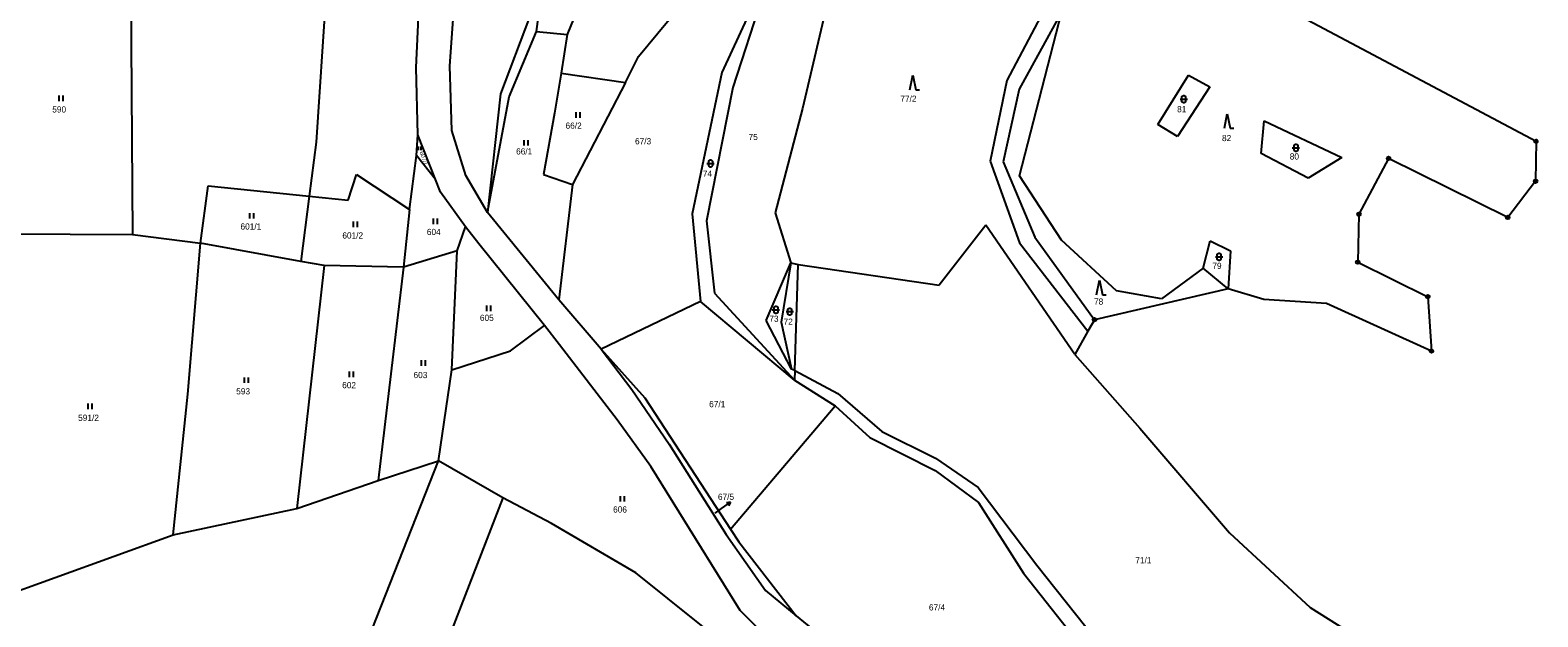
# Model space of a CAD drawing. Extents: x -794421 to -792735, y -1117671 to -1115559.
# Drawn here: x -793344.4 to -792931.3, y -1117405.7 to -1117244.8 of the extents above; entities that cross this region are included whole.
import ezdxf

# ---------------------------------------------------------------- set-up
doc = ezdxf.new("R2010")
doc.units = 0
for name, color, linetype in [('Komunikace', 7, 'Continuous'), ('Vrstva 1', 7, 'Continuous'), ('Vrstva 14', 7, 'Continuous'), ('Vrstva 16', 7, 'Continuous'), ('Vrstva 23', 7, 'Continuous'), ('Vrstva 28', 7, 'Continuous'), ('Vrstva 4', 7, 'Continuous')]:
    doc.layers.add(name, color=color, linetype=linetype)

msp = doc.modelspace()

# ---------------------------------------------------------------- linework, layer by layer
at = {"layer": 'Komunikace'}
msp.add_line((-793156.69, -1117377.21), (-793154.95, -1117375.97), dxfattribs=at)
at = {"layer": 'Vrstva 1'}
for p, q in [((-793260.9, -1117198.31), (-793266.07, -1117275.47)), ((-793238.67, -1117254.97), (-793236.5, -1117210.76)), ((-793229.4, -1117254.52), (-793226.18, -1117209.72)), ((-793205.62, -1117245.12), (-793201.81, -1117214.94)), ((-793316.98, -1117218.04), (-793316.4, -1117300.84)), ((-793185.17, -1117216.32), (-793197.22, -1117245.93)), ((-793140.12, -1117224.4), (-793154.91, -1117256.34)), ((-793140.12, -1117224.4), (-793151.88, -1117260.51)), ((-793177.68, -1117252.02), (-793160.21, -1117230.85)), ((-793124.49, -1117230.97), (-793132.78, -1117266.28)), ((-793066.62, -1117239.34), (-793076.81, -1117258.54)), ((-793061.68, -1117239.68), (-793073.4, -1117260.98)), ((-793073.28, -1117284.7), (-793061.68, -1117239.68)), ((-793207.55, -1117241.17), (-793215.51, -1117262.2)), ((-793213.19, -1117263.04), (-793205.62, -1117245.12)), ((-793205.62, -1117245.12), (-793197.22, -1117245.93)), ((-793197.22, -1117245.93), (-793198.88, -1117256.57)), ((-793181.29, -1117259.16), (-793177.68, -1117252.02)), ((-793238.16, -1117273.44), (-793238.67, -1117254.97)), ((-793228.88, -1117272.27), (-793229.4, -1117254.52)), ((-793198.88, -1117256.57), (-793200.71, -1117267.55)), ((-793198.88, -1117256.57), (-793181.29, -1117259.16)), ((-793154.91, -1117256.34), (-793162.97, -1117295.13)), ((-793181.29, -1117259.16), (-793195.79, -1117287.12)), ((-793151.88, -1117260.51), (-793159.06, -1117297.11)), ((-793076.81, -1117258.54), (-793081.38, -1117280.68)), ((-793035.38, -1117270.69), (-793026.97, -1117257.13)), ((-793021.19, -1117260.36), (-793030.06, -1117273.9)), ((-793026.97, -1117257.13), (-793021.19, -1117260.36)), ((-793215.51, -1117262.2), (-793219.06, -1117294.74)), ((-793219.06, -1117294.74), (-793213.19, -1117263.04)), ((-793073.4, -1117260.98), (-793077.81, -1117280.91)), ((-793200.71, -1117267.55), (-793203.78, -1117284.33)), ((-793132.78, -1117266.28), (-793140.29, -1117294.91)), ((-793224.98, -1117284.66), (-793228.88, -1117272.27)), ((-793030.06, -1117273.9), (-793035.38, -1117270.69)), ((-793007.13, -1117278.56), (-793006.27, -1117269.65)), ((-793006.27, -1117269.65), (-792985.02, -1117279.68)), ((-793266.07, -1117275.47), (-793267.95, -1117290.3)), ((-793238.58, -1117279.17), (-793238.16, -1117273.44)), ((-793233.31, -1117285.75), (-793238.16, -1117273.44)), ((-793240.45, -1117293.93), (-793238.58, -1117279.17)), ((-793233.31, -1117285.75), (-793238.58, -1117279.17)), ((-793081.38, -1117280.68), (-793073.29, -1117303.06)), ((-793077.81, -1117280.91), (-793069.13, -1117301.58)), ((-792994.18, -1117285.34), (-793007.13, -1117278.56)), ((-792985.02, -1117279.68), (-792994.18, -1117285.34)), ((-793257.31, -1117291.39), (-793254.98, -1117284.33)), ((-793254.98, -1117284.33), (-793240.45, -1117293.93)), ((-793219.06, -1117294.74), (-793224.98, -1117284.66)), ((-793203.78, -1117284.33), (-793195.79, -1117287.12)), ((-793061.82, -1117302.35), (-793073.28, -1117284.7)), ((-793297.72, -1117303.18), (-793295.63, -1117287.48)), ((-793295.63, -1117287.48), (-793267.95, -1117290.3)), ((-793231.95, -1117289.21), (-793233.31, -1117285.75)), ((-793225.14, -1117298.73), (-793231.95, -1117289.21)), ((-793195.79, -1117287.12), (-793199.58, -1117318.7)), ((-793267.95, -1117290.3), (-793270.21, -1117308.18)), ((-793267.95, -1117290.3), (-793257.31, -1117291.39)), ((-793240.45, -1117293.93), (-793242.13, -1117309.8)), ((-793199.58, -1117318.7), (-793219.06, -1117294.74)), ((-793162.97, -1117295.13), (-793160.75, -1117319.21)), ((-793159.06, -1117297.11), (-793156.85, -1117316.94)), ((-793140.29, -1117294.91), (-793135.99, -1117308.56)), ((-793350.56, -1117300.6), (-793316.4, -1117300.84)), ((-793316.4, -1117300.84), (-793297.72, -1117303.18)), ((-793227.44, -1117305.29), (-793225.14, -1117298.73)), ((-793221.42, -1117303.41), (-793225.14, -1117298.73)), ((-793082.51, -1117298.26), (-793095.28, -1117314.74)), ((-793058.15, -1117333.75), (-793082.51, -1117298.26)), ((-793069.13, -1117301.58), (-793052.78, -1117324.18)), ((-793301.19, -1117344.58), (-793297.72, -1117303.18)), ((-793270.21, -1117308.18), (-793297.72, -1117303.18)), ((-793227.44, -1117305.29), (-793242.13, -1117309.8)), ((-793228.88, -1117337.91), (-793227.44, -1117305.29)), ((-793203.49, -1117325.78), (-793221.42, -1117303.41)), ((-793073.29, -1117303.06), (-793054.62, -1117327.3)), ((-793046.75, -1117316.31), (-793061.82, -1117302.35)), ((-793023.01, -1117310.05), (-793021.11, -1117302.53)), ((-793021.11, -1117302.53), (-793015.54, -1117305.32)), ((-793015.54, -1117305.32), (-793016.16, -1117315.69)), ((-793263.8, -1117309.35), (-793271.37, -1117375.94)), ((-793263.8, -1117309.35), (-793270.21, -1117308.18)), ((-793242.13, -1117309.8), (-793263.8, -1117309.35)), ((-793242.13, -1117309.8), (-793249.06, -1117368.3)), ((-793142.76, -1117324.44), (-793135.99, -1117308.56)), ((-793135.99, -1117308.56), (-793138.59, -1117324.87)), ((-793135.99, -1117308.56), (-793133.98, -1117309.03)), ((-793134.88, -1117338.16), (-793133.98, -1117309.03)), ((-793133.98, -1117309.03), (-793095.28, -1117314.74)), ((-793023.01, -1117310.05), (-793034.37, -1117318.45)), ((-793016.16, -1117315.69), (-793023.01, -1117310.05)), ((-793156.85, -1117316.94), (-793134.94, -1117340.8)), ((-793034.37, -1117318.45), (-793046.75, -1117316.31)), ((-793187.95, -1117332.28), (-793199.58, -1117318.7)), ((-793160.75, -1117319.21), (-793187.95, -1117332.28)), ((-793134.94, -1117340.8), (-793160.75, -1117319.21)), ((-793212.82, -1117332.77), (-793203.49, -1117325.78)), ((-793199.36, -1117331.07), (-793203.49, -1117325.78)), ((-793135.77, -1117337.72), (-793142.76, -1117324.44)), ((-793138.59, -1117324.87), (-793135.77, -1117337.72)), ((-793228.88, -1117337.91), (-793212.82, -1117332.77)), ((-793183.54, -1117351.62), (-793199.36, -1117331.07)), ((-793187.95, -1117332.28), (-793179.51, -1117343.3)), ((-793187.95, -1117332.28), (-793175.97, -1117345.66)), ((-793232.53, -1117362.94), (-793228.88, -1117337.91)), ((-793134.88, -1117338.16), (-793135.77, -1117337.72)), ((-793134.88, -1117338.16), (-793134.94, -1117340.8)), ((-793134.88, -1117338.16), (-793123.08, -1117344.47)), ((-793179.51, -1117343.3), (-793169.32, -1117358.3)), ((-793134.94, -1117340.8), (-793123.84, -1117347.81)), ((-793305.2, -1117383.22), (-793301.19, -1117344.58)), ((-793175.97, -1117345.66), (-793152.46, -1117381.62)), ((-793123.08, -1117344.47), (-793111.04, -1117354.84)), ((-793152.46, -1117381.62), (-793123.84, -1117347.81)), ((-793123.84, -1117347.81), (-793114.3, -1117356.53)), ((-793174.35, -1117364.49), (-793183.54, -1117351.62)), ((-793111.04, -1117354.84), (-793096.35, -1117362.17)), ((-793169.32, -1117358.3), (-793153.71, -1117383.1)), ((-793114.3, -1117356.53), (-793096.39, -1117365.52)), ((-793286.1, -1117499.19), (-793232.53, -1117362.94)), ((-793249.06, -1117368.3), (-793232.53, -1117362.94)), ((-793214.85, -1117373.01), (-793232.53, -1117362.94)), ((-793096.35, -1117362.17), (-793084.66, -1117370.19)), ((-793149.83, -1117403.92), (-793174.35, -1117364.49)), ((-793096.39, -1117365.52), (-793084.58, -1117374.33)), ((-793271.37, -1117375.94), (-793249.06, -1117368.3)), ((-793084.66, -1117370.19), (-793068.56, -1117391.53)), ((-793305.2, -1117383.22), (-793271.37, -1117375.94)), ((-793214.85, -1117373.01), (-793268.27, -1117510.87)), ((-793201.55, -1117380.12), (-793214.85, -1117373.01)), ((-793084.58, -1117374.33), (-793072.2, -1117393.73)), ((-793178.43, -1117393.62), (-793201.55, -1117380.12)), ((-793357.1, -1117401.96), (-793305.2, -1117383.22)), ((-793153.71, -1117383.1), (-793142.93, -1117398.44)), ((-793152.46, -1117381.62), (-793150.19, -1117385.09)), ((-793150.19, -1117385.09), (-793134.52, -1117405.39)), ((-793068.56, -1117391.53), (-793048.75, -1117416.41)), ((-793143.2, -1117421.9), (-793178.43, -1117393.62)), ((-793072.2, -1117393.73), (-793051.64, -1117419.77)), ((-793142.93, -1117398.44), (-793134.52, -1117405.39)), ((-793136.06, -1117417.71), (-793149.83, -1117403.92)), ((-793134.52, -1117405.39), (-793123.59, -1117414.41))]:
    msp.add_line(p, q, dxfattribs=at)
at = {"layer": 'Vrstva 16'}
for p, q in [((-793154.95, -1117375.97), (-793152.507, -1117374.228)), ((-793152.507, -1117374.228), (-793153.611, -1117374.401)), ((-793152.507, -1117374.228), (-793153.031, -1117375.216))]:
    msp.add_line(p, q, dxfattribs=at)
at = {"layer": 'Vrstva 23'}
for p, q in [((-793103.34, -1117261.12), (-793102.54, -1117257.12)), ((-793102.54, -1117257.12), (-793101.74, -1117261.12)), ((-793336.46, -1117264.22), (-793336.46, -1117262.72)), ((-793335.46, -1117262.72), (-793335.46, -1117264.22)), ((-793101.74, -1117261.12), (-793100.74, -1117261.12)), ((-793029.3, -1117263.7), (-793027.3, -1117263.7)), ((-793028.8, -1117263.1), (-793028.7, -1117262.9)), ((-793028.8, -1117264.3), (-793028.8, -1117263.1)), ((-793028.7, -1117264.5), (-793028.8, -1117264.3)), ((-793028.7, -1117262.9), (-793028.6, -1117262.8)), ((-793028.6, -1117264.6), (-793028.7, -1117264.5)), ((-793028.6, -1117262.8), (-793028.4, -1117262.7)), ((-793028.4, -1117264.7), (-793028.6, -1117264.6)), ((-793028.4, -1117262.7), (-793028.2, -1117262.7)), ((-793028.2, -1117264.7), (-793028.4, -1117264.7)), ((-793028.2, -1117262.7), (-793028, -1117262.8)), ((-793028, -1117264.6), (-793028.2, -1117264.7)), ((-793028, -1117262.8), (-793027.9, -1117262.9)), ((-793027.9, -1117264.5), (-793028, -1117264.6)), ((-793027.9, -1117262.9), (-793027.8, -1117263.1)), ((-793027.8, -1117264.3), (-793027.9, -1117264.5)), ((-793027.8, -1117263.1), (-793027.8, -1117264.3)), ((-793194.8, -1117268.81), (-793194.8, -1117267.31)), ((-793193.8, -1117267.31), (-793193.8, -1117268.81)), ((-793017.18, -1117271.68), (-793016.38, -1117267.68)), ((-793016.38, -1117267.68), (-793015.58, -1117271.68)), ((-793015.58, -1117271.68), (-793014.58, -1117271.68)), ((-793238.035, -1117277.72), (-793238.035, -1117276.715)), ((-793237.365, -1117276.715), (-793237.365, -1117277.72)), ((-793209, -1117276.43), (-793209, -1117274.93)), ((-793208, -1117274.93), (-793208, -1117276.43)), ((-792998.57, -1117277.02), (-792996.57, -1117277.02)), ((-792998.07, -1117276.42), (-792997.97, -1117276.22)), ((-792998.07, -1117277.62), (-792998.07, -1117276.42)), ((-792997.97, -1117276.22), (-792997.87, -1117276.12)), ((-792997.87, -1117276.12), (-792997.67, -1117276.02)), ((-792997.67, -1117276.02), (-792997.47, -1117276.02)), ((-792997.47, -1117276.02), (-792997.27, -1117276.12)), ((-792997.27, -1117276.12), (-792997.17, -1117276.22)), ((-792997.17, -1117276.22), (-792997.07, -1117276.42)), ((-792997.07, -1117276.42), (-792997.07, -1117277.62)), ((-793158.98, -1117281.32), (-793156.98, -1117281.32)), ((-793158.48, -1117280.72), (-793158.38, -1117280.52)), ((-793158.48, -1117281.92), (-793158.48, -1117280.72)), ((-793158.38, -1117280.52), (-793158.28, -1117280.42)), ((-793158.28, -1117280.42), (-793158.08, -1117280.32)), ((-793158.08, -1117280.32), (-793157.88, -1117280.32)), ((-793157.88, -1117280.32), (-793157.68, -1117280.42)), ((-793157.68, -1117280.42), (-793157.58, -1117280.52)), ((-793157.58, -1117280.52), (-793157.48, -1117280.72)), ((-793157.48, -1117280.72), (-793157.48, -1117281.92)), ((-792997.97, -1117277.82), (-792998.07, -1117277.62)), ((-792997.87, -1117277.92), (-792997.97, -1117277.82)), ((-792997.67, -1117278.02), (-792997.87, -1117277.92)), ((-792997.47, -1117278.02), (-792997.67, -1117278.02)), ((-792997.27, -1117277.92), (-792997.47, -1117278.02)), ((-792997.17, -1117277.82), (-792997.27, -1117277.92)), ((-792997.07, -1117277.62), (-792997.17, -1117277.82)), ((-793158.38, -1117282.12), (-793158.48, -1117281.92)), ((-793158.28, -1117282.22), (-793158.38, -1117282.12)), ((-793158.08, -1117282.32), (-793158.28, -1117282.22)), ((-793157.88, -1117282.32), (-793158.08, -1117282.32)), ((-793157.68, -1117282.22), (-793157.88, -1117282.32)), ((-793157.58, -1117282.12), (-793157.68, -1117282.22)), ((-793157.48, -1117281.92), (-793157.58, -1117282.12)), ((-793284.24, -1117296.46), (-793284.24, -1117294.96)), ((-793283.24, -1117294.96), (-793283.24, -1117296.46)), ((-793255.84, -1117298.79), (-793255.84, -1117297.29)), ((-793254.84, -1117297.29), (-793254.84, -1117298.79)), ((-793233.86, -1117297.97), (-793233.86, -1117296.47)), ((-793232.86, -1117296.47), (-793232.86, -1117297.97)), ((-793019.12, -1117306.34), (-793019.02, -1117306.14)), ((-793019.02, -1117306.14), (-793018.92, -1117306.04)), ((-793018.92, -1117306.04), (-793018.72, -1117305.94)), ((-793018.72, -1117305.94), (-793018.52, -1117305.94)), ((-793018.52, -1117305.94), (-793018.32, -1117306.04)), ((-793018.32, -1117306.04), (-793018.22, -1117306.14)), ((-793018.22, -1117306.14), (-793018.12, -1117306.34)), ((-793019.62, -1117306.94), (-793017.62, -1117306.94)), ((-793019.12, -1117307.54), (-793019.12, -1117306.34)), ((-793019.02, -1117307.74), (-793019.12, -1117307.54)), ((-793018.92, -1117307.84), (-793019.02, -1117307.74)), ((-793018.72, -1117307.94), (-793018.92, -1117307.84)), ((-793018.52, -1117307.94), (-793018.72, -1117307.94)), ((-793018.32, -1117307.84), (-793018.52, -1117307.94)), ((-793018.22, -1117307.74), (-793018.32, -1117307.84)), ((-793018.12, -1117307.54), (-793018.22, -1117307.74)), ((-793018.12, -1117306.34), (-793018.12, -1117307.54)), ((-793052.2, -1117317.39), (-793051.4, -1117313.39)), ((-793051.4, -1117313.39), (-793050.6, -1117317.39)), ((-793050.6, -1117317.39), (-793049.6, -1117317.39)), ((-793219.28, -1117321.83), (-793219.28, -1117320.33)), ((-793218.28, -1117320.33), (-793218.28, -1117321.83)), ((-793141.05, -1117321.46), (-793139.05, -1117321.46)), ((-793140.55, -1117320.86), (-793140.45, -1117320.66)), ((-793140.55, -1117322.06), (-793140.55, -1117320.86)), ((-793140.45, -1117322.26), (-793140.55, -1117322.06)), ((-793140.45, -1117320.66), (-793140.35, -1117320.56)), ((-793140.35, -1117322.36), (-793140.45, -1117322.26)), ((-793140.35, -1117320.56), (-793140.15, -1117320.46)), ((-793140.15, -1117322.46), (-793140.35, -1117322.36)), ((-793140.15, -1117320.46), (-793139.95, -1117320.46)), ((-793139.95, -1117322.46), (-793140.15, -1117322.46)), ((-793139.95, -1117320.46), (-793139.75, -1117320.56)), ((-793139.75, -1117322.36), (-793139.95, -1117322.46)), ((-793139.75, -1117320.56), (-793139.65, -1117320.66)), ((-793139.65, -1117322.26), (-793139.75, -1117322.36)), ((-793139.65, -1117320.66), (-793139.55, -1117320.86)), ((-793139.55, -1117322.06), (-793139.65, -1117322.26)), ((-793139.55, -1117320.86), (-793139.55, -1117322.06)), ((-793137.27, -1117321.98), (-793135.27, -1117321.98)), ((-793136.77, -1117321.38), (-793136.67, -1117321.18)), ((-793136.77, -1117322.58), (-793136.77, -1117321.38)), ((-793136.67, -1117322.78), (-793136.77, -1117322.58)), ((-793136.67, -1117321.18), (-793136.57, -1117321.08)), ((-793136.57, -1117321.08), (-793136.37, -1117320.98)), ((-793136.37, -1117320.98), (-793136.17, -1117320.98)), ((-793136.17, -1117320.98), (-793135.97, -1117321.08)), ((-793135.97, -1117321.08), (-793135.87, -1117321.18)), ((-793135.87, -1117321.18), (-793135.77, -1117321.38)), ((-793135.77, -1117322.58), (-793135.87, -1117322.78)), ((-793135.77, -1117321.38), (-793135.77, -1117322.58)), ((-793136.57, -1117322.88), (-793136.67, -1117322.78)), ((-793136.37, -1117322.98), (-793136.57, -1117322.88)), ((-793136.17, -1117322.98), (-793136.37, -1117322.98)), ((-793135.97, -1117322.88), (-793136.17, -1117322.98)), ((-793135.87, -1117322.78), (-793135.97, -1117322.88)), ((-793256.9, -1117339.91), (-793256.9, -1117338.41)), ((-793255.9, -1117338.41), (-793255.9, -1117339.91)), ((-793237.15, -1117336.83), (-793237.15, -1117335.33)), ((-793236.15, -1117335.33), (-793236.15, -1117336.83)), ((-793285.69, -1117341.5), (-793285.69, -1117340)), ((-793284.69, -1117340), (-793284.69, -1117341.5)), ((-793328.47, -1117348.69), (-793328.47, -1117347.19)), ((-793327.47, -1117347.19), (-793327.47, -1117348.69)), ((-793182.61, -1117374.06), (-793182.61, -1117372.56)), ((-793181.61, -1117372.56), (-793181.61, -1117374.06))]:
    msp.add_line(p, q, dxfattribs=at)
at = {"layer": 'Vrstva 28'}
for centre, radius in [((-792931.78, -1117275.26), 0.5), ((-792931.78, -1117275.26), 0.01), ((-792972.2, -1117279.95), 0.5), ((-792972.2, -1117279.95), 0.01), ((-792931.89, -1117286.22), 0.5), ((-792931.89, -1117286.22), 0.01), ((-792980.29, -1117295.25), 0.5), ((-792980.29, -1117295.25), 0.01), ((-792939.52, -1117296.14), 0.5), ((-792939.52, -1117296.14), 0.01), ((-792980.63, -1117308.41), 0.5), ((-792980.63, -1117308.41), 0.01), ((-792961.4, -1117317.88), 0.5), ((-792961.4, -1117317.88), 0.01), ((-793052.78, -1117324.18), 0.5), ((-793052.78, -1117324.18), 0.01), ((-792960.45, -1117332.78), 0.5), ((-792960.45, -1117332.78), 0.01)]:
    msp.add_circle(centre, radius, dxfattribs=at)
at = {"layer": 'Vrstva 4'}
for p, q in [((-793000.25, -1117238.87), (-792931.78, -1117275.26)), ((-792931.78, -1117275.26), (-792931.89, -1117286.22)), ((-792972.2, -1117279.95), (-792980.29, -1117295.25)), ((-792939.52, -1117296.14), (-792972.2, -1117279.95)), ((-792931.89, -1117286.22), (-792939.52, -1117296.14)), ((-792980.29, -1117295.25), (-792980.63, -1117308.41)), ((-792980.63, -1117308.41), (-792961.4, -1117317.88)), ((-793016.16, -1117315.69), (-793052.78, -1117324.18)), ((-793006.32, -1117318.69), (-793016.16, -1117315.69)), ((-792961.4, -1117317.88), (-792960.45, -1117332.78)), ((-792989.16, -1117319.75), (-793006.32, -1117318.69)), ((-792960.45, -1117332.78), (-792989.16, -1117319.75)), ((-793052.78, -1117324.18), (-793054.62, -1117327.3)), ((-793054.62, -1117327.3), (-793058.15, -1117333.75)), ((-793058.15, -1117333.75), (-793040.38, -1117353.96)), ((-793040.38, -1117353.96), (-793015.77, -1117382.69)), ((-793015.77, -1117382.69), (-792993.66, -1117403.11)), ((-792993.66, -1117403.11), (-792957.73, -1117425.76))]:
    msp.add_line(p, q, dxfattribs=at)

# ---------------------------------------------------------------- texts
at = {"layer": 'Vrstva 14'}
for s, height, p in [('77/2', 1.7, (-793105.963, -1117264.42)), ('590', 1.7, (-793338.342, -1117267.36)), ('81', 1.7, (-793030.12, -1117267.3)), ('66/2', 1.7, (-793197.7, -1117271.81)), ('66/1', 1.7, (-793211.253, -1117278.87)), ('67/3', 1.7, (-793178.667, -1117276.09)), ('75', 1.7, (-793147.55, -1117274.91)), ('82', 1.7, (-793017.826, -1117275.21)), ('80', 1.7, (-792999.256, -1117280.26)), ('74', 1.7, (-793160.079, -1117284.97)), ('601/1', 1.7, (-793286.766, -1117299.47)), ('601/2', 1.7, (-793258.862, -1117301.93)), ('604', 1.7, (-793235.702, -1117300.97)), ('79', 1.7, (-793020.463, -1117310.26)), ('78', 1.7, (-793052.893, -1117320.07)), ('605', 1.7, (-793221.162, -1117324.52)), ('73', 1.7, (-793141.863, -1117324.77)), ('72', 1.7, (-793137.963, -1117325.58)), ('603', 1.7, (-793239.366, -1117340.21)), ('593', 1.7, (-793287.943, -1117344.68)), ('602', 1.7, (-793258.906, -1117342.99)), ('67/1', 1.7, (-793158.35, -1117348.2)), ('591/2', 1.7, (-793331.249, -1117351.94)), ('606', 1.7, (-793184.676, -1117377.09)), ('67/5', 0.1, (-793156.856, -1117377.21)), ('71/1', 1.7, (-793041.583, -1117391.02)), ('67/4', 1.7, (-793098.132, -1117403.95))]:
    msp.add_text(s, height=height, dxfattribs=at).set_placement(p)
msp.add_text('607/1', height=1.14, rotation=291.49443, dxfattribs=at).set_placement((-793237.713, -1117278.265))
at = {"layer": 'Vrstva 16'}
msp.add_text('67/5', height=1.7, dxfattribs=at).set_placement((-793155.94, -1117373.61))

doc.saveas('drawing.dxf')
